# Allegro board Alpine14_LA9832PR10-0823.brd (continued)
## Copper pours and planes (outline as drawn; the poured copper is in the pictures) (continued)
SLEEVE on IN3 (solid shape): 256.39,148.45 256.39,148.03 256.39,147.23 256.56,147.06 256.96,147.06 256.96,146.04 255.31,146.04 254.99,146.36 254.99,148.33 255.24,148.58 256.26,148.58
SLEEVE on TOP: 303.68,155.98 303.68,157.42 303.88,157.62 305.4,157.62 305.52,157.49 305.52,156.59 305.37,156.44 305.05,156.44 304.44,155.83 303.83,155.83
SNUB_1.35V on TOP (solid shape): 184.89,81.78 184.89,79.05 184.76,78.92 183.74,78.92 183.49,79.18 183.49,81.78 183.62,81.91 184.76,81.91
SW1 on TOP (solid shape): 190.85,146.09 190.59,145.83 190.59,144.21 190.52,144.14 190.4,144.14 190.35,144.19 190.35,145.16 190.3,145.2 189.94,145.57 189.94,147.11 189.95,147.12 190.85,147.12
SW1 on TOP (solid shape): 202.54,150.68 202.54,149.6 202.92,149.22 206.68,149.22 206.93,148.96 206.93,142.97 206.45,142.48 204.44,142.48 204.31,142.61 203.3,142.61 203.17,142.74 203.17,144.39 203.3,144.52 204.31,144.52 204.57,144.77 204.57,146.04 204.31,146.29 202.03,146.29 201.9,146.42 201.9,149.09 201.9,149.09 201.65,149.34 201.65,150.74 201.71,150.8 202.41,150.8
SW1 on BOTTOM (solid shape): outline of 89 points within 199.49,141.85 204.95,148.58
SW1 on IN3 (solid shape): 203.43,148.52 203.43,148.2 203.3,148.07 202.41,148.07 201.46,149.03 201.46,149.34 201.65,149.53 202.41,149.53
SW1 on IN3 (solid shape): 191.81,147.37 191.81,146.61 190.47,145.28 190.16,145.28 190.03,145.41 190.03,146.42 191.05,147.44 191.74,147.44
SW2 on TOP (solid shape): 205.84,140.83 205.84,135.75 205.59,135.5 204.37,135.5 202.58,133.7 201.91,133.7 201.81,133.8 201.81,137.79 203.2,139.18 203.2,140.8 203.36,140.96 205.71,140.96
SW2 on TOP (solid shape): 190.53,141.99 190.57,141.94 190.57,140.83 190.62,140.78 190.62,138.9 190.55,138.83 189.71,138.83 189.63,138.9 189.63,139.54 190.17,140.07 190.17,140.81 190.35,140.99 190.35,141.95 190.38,141.99 190.5,141.99
SW2 on BOTTOM (solid shape): 205.52,139.95 205.52,138.99 203.94,137.41 203.94,135.31 203.3,134.67 199.3,134.67 199.2,134.78 199.2,138.13 199.62,138.55 199.62,139.56 200.19,140.14 205.33,140.14
SW2 on IN3 (solid shape): 202.79,137.53 202.79,136.71 202.67,136.58 201.4,136.58 201.33,136.64 201.33,137.6 201.4,137.66 202.67,137.66
SW2 on IN3 (solid shape): 190.98,140.71 190.98,139.95 191.36,139.56 191.36,138.74 190.79,138.74 190.09,139.44 190.09,140.77 190.22,140.9 190.79,140.9
SW_1.35V on TOP (solid shape): 184.63,78.29 184.63,75.94 184.25,75.56 182.22,75.56 182.09,75.68 182.09,76.57 182.22,76.7 183.23,76.7 183.49,76.95 183.49,78.22 183.62,78.35 184.57,78.35
SW_1.35V on TOP (solid shape): 177.16,81.22 177.16,80.36 177.37,80.15 178.24,80.15 178.57,79.82 178.57,76.35 178.41,76.19 177.77,76.19 177.65,76.32 177.65,78.4 177.56,78.48 177.56,78.49 177.48,78.59 177.38,78.67 177.37,78.67 176.71,79.34 176.71,80.83 176.57,80.97 176.31,80.97 176.13,81.15 176.13,81.23 176.2,81.29 177.09,81.29
SW_1.35V on BOTTOM (solid shape): 186.22,81.02 186.22,79.89 186.44,79.67 189.15,79.67 189.53,79.29 189.53,75.68 191.93,73.28 191.93,68 191.49,67.55 187.43,67.55 186.92,68.06 186.92,72.63 183.71,75.84 186.37,75.84 186.37,75.78 186.38,75.73 186.4,75.68 186.42,75.63 186.45,75.59 186.48,75.55 186.53,75.52 186.57,75.49 186.62,75.47 186.67,75.46 186.73,75.45 186.78,75.46 186.83,75.47 186.88,75.49 186.93,75.52 186.97,75.55 187.01,75.59 187.04,75.63 187.06,75.68 187.08,75.73 187.08,75.78 187.08,75.84 187.08,75.89 187.06,75.94 187.04,75.99 187.01,76.03 186.97,76.07 186.93,76.1 186.88,76.13 186.83,76.15 186.78,76.16 186.73,76.17 186.67,76.16 186.62,76.15 186.57,76.13 186.53,76.1 186.48,76.07 186.45,76.03 186.42,75.99 186.4,75.94 186.38,75.89 186.37,75.84 183.71,75.84 183.49,76.06 183.49,81.02 183.73,81.26 185.98,81.26
SW_++VDDRP on TOP (solid shape): 44.68,38.47 44.68,36.95 44.42,36.69 43.66,36.69 43.28,37.08 43.28,38.73 43.53,38.98 44.17,38.98
SW_++VDDRP on TOP (solid shape): 41.31,31.8 41.31,30.98 41.19,30.85 39.09,30.85 38.9,31.04 38.9,31.17 39.66,31.93 41.19,31.93
SW_++VDDRP on BOTTOM (solid shape): 40.26,31.31 40.26,29.56 40.13,29.43 39.14,29.43 39.06,29.51 39.06,30.04 39.12,30.09 39.52,30.09 39.65,30.22 39.65,30.65 39.5,30.8 38.99,30.8 38.91,30.88 38.91,31.21 39.06,31.36 40.21,31.36
SW_++VDDRP on BOTTOM (solid shape): 47.79,41.33 47.79,37.16 47.73,37.1 46.96,37.1 46.87,37.18 46.87,38.25 46.65,38.47 46.22,38.47 46.2,38.5 45.96,38.64 45.72,38.5 45.7,38.47 45.31,38.47 45.12,38.28 45.12,37.08 44.93,36.88 43.15,36.88 41.95,35.68 39.47,35.68 39.41,35.74 39.41,41.77 39.98,42.35 46.77,42.35
SW_+V1.05SP on TOP (solid shape): 149.96,80.13 149.96,78.99 149.9,78.92 148.94,78.92 148.88,78.86 147.93,78.86 147.87,78.92 147.87,79.75 147.93,79.81 148.88,79.81 149.26,80.19 149.9,80.19
SW_+V1.05SP on BOTTOM (solid shape): 151.1,81.08 151.1,79.24 151.04,79.18 149.45,79.18 148.94,78.67 148.94,76.51 148.82,76.38 146.21,76.38 146.02,76.57 146.02,81.02 146.21,81.21 150.98,81.21
U2_BOOT1 on BOTTOM (solid shape): 60.43,38.66 58.97,37.2 58.97,36.5 58.9,36.44 58.01,36.44 57.95,36.5 57.95,36.63 58.01,36.69 58.2,36.69 58.46,36.95 58.46,37.58 59.6,38.73 59.6,40 60.43,40
U2_LGATE1 on TOP (solid shape): 57.95,40.19 57.95,38.15 57.82,38.03 57.25,38.03 57.19,38.09 57.19,40.06 57.38,40.25 57.89,40.25
U2_LGATE1 on TOP (solid shape): 68.43,42.35 68.43,41.46 68.3,41.33 66.65,41.33 66.65,41.77 67.35,42.47 68.3,42.47
U2_LGATE1 on BOTTOM (solid shape): 69.25,42.41 69.25,41.39 69.13,41.27 68.11,41.27 67.98,41.39 67.98,42.41 68.11,42.54 69.13,42.54
U2_LGATE1 on BOTTOM (solid shape): 74.84,42.41 74.84,41.39 74.71,41.27 73.7,41.27 73.57,41.39 73.57,42.41 73.7,42.54 74.71,42.54
U2_LGATE1 on BOTTOM (solid shape): 58.01,39.36 57.82,39.17 57.82,38.33 57.38,37.89 57.38,36.82 57.3,36.74 57.17,36.74 57.1,36.82 57.1,39.23 57.4,39.54 57.4,40.06 58.01,40.06
U2_LGATE1 on IN1 (solid shape): 74.08,42.35 74.08,41.46 73.95,41.33 68.11,41.33 67.98,41.46 67.98,42.35 68.11,42.47 73.95,42.47
U2_LGATE2 on TOP (solid shape): 56.3,39.81 56.3,38.03 56.17,37.9 55.54,37.9 55.47,37.96 55.47,38.92 55.35,39.04 55.35,39.87 55.41,39.93 56.17,39.93
U2_LGATE2 on TOP (solid shape): 56.36,44.25 56.36,43.43 56.23,43.3 55.47,43.3 55.22,43.04 55.22,42.54 54.2,42.54 54.2,43.81 54.84,44.44 56.17,44.44
U2_LGATE2 on BOTTOM (solid shape): 51.41,44.38 51.41,43.36 51.28,43.23 50.27,43.23 50.14,43.36 50.14,44.38 50.27,44.5 51.28,44.5
U2_LGATE2 on BOTTOM (solid shape): 57.12,44.38 57.12,43.36 57,43.23 55.98,43.23 55.85,43.36 55.85,44.38 55.98,44.5 57,44.5
U2_LGATE2 on IN1 (solid shape): 56.36,44.25 56.36,43.49 56.17,43.3 50.27,43.3 50.14,43.43 50.14,44.31 50.27,44.44 56.17,44.44
U2_PHASE1 on BOTTOM (solid shape): 59.22,38.73 58.14,37.65 58.14,37.08 57.82,36.76 57.7,36.76 57.63,36.82 57.63,37.84 58.08,38.28 58.08,39.11 58.33,39.36 58.33,40.06 59.22,40.06
U2_PHASE1 on BOTTOM (solid shape): 75.86,51.93 77.06,51.93 77.32,51.68 77.32,48.76 78.08,48 81.13,48 81.19,47.93 81.19,46.35 80.94,46.09 79.35,46.09 78.71,45.46 78.71,43.62 78.46,43.36 68.49,43.36 68.24,43.62 68.24,53.01 68.81,53.59 74.21,53.59
U2_PHASE1 on IN1 (solid shape): 60.55,39.3 60.55,38.41 60.17,38.03 58.27,38.03 58.01,38.28 58.01,39.04 58.39,39.42 60.43,39.42
U2_PHASE1 on IN1 (solid shape): 70.49,49.23 70.49,48.69 69.24,47.43 68.6,47.43 68.45,47.58 68.45,48.17 69.56,49.27 70.45,49.27
U2_PHASE2 on TOP (solid shape): 52.04,46.98 52.04,46.47 51.79,46.22 51.28,46.22 50.27,47.24 50.27,48.06 50.46,48.25 50.77,48.25
U2_PHASE2 on TOP (solid shape): 55.16,38.92 55.16,38.09 55.03,37.96 54.46,37.96 53.25,39.17 53.25,39.74 53.5,40 54.08,40
U2_PHASE2 on BOTTOM (solid shape): 54.9,39.42 55.22,39.11 55.22,38.09 55.09,37.96 54.58,37.96 54.39,38.15 54.39,38.73 54.01,39.11 54.01,40.19 54.9,40.19
U2_PHASE2 on BOTTOM (solid shape): 60.36,56 60.36,54.47 60.74,54.09 62.01,54.09 62.14,53.97 62.14,51.11 60.93,49.9 60.93,45.58 60.68,45.33 50.96,45.33 50.96,46.73 50.52,47.17 48.68,47.17 48.42,47.43 48.42,49.33 50.08,49.33 50.46,49.71 50.46,56.06 50.71,56.32 60.04,56.32
U2_UGATE1 on BOTTOM (solid shape): 76.75,53.46 77.06,53.46 77.25,53.27 77.25,52.63 77.13,52.51 75.86,52.51 75.48,52.89 75.48,53.65 75.67,53.84 76.36,53.84
U2_UGATE1 on IN1 (solid shape): 61.25,37.36 61.25,36.15 61.19,36.09 59.47,36.09 59.22,36.34 59.22,37.36 59.33,37.47 61.14,37.47
U2_UGATE1 on IN1 (solid shape): 76.49,53.71 76.49,52.76 75.35,51.62 74.59,51.62 74.52,51.68 74.52,52.76 75.67,53.9 76.3,53.9
U2_UGATE2 on TOP (solid shape): 62.08,56.06 62.08,55.43 61.89,55.24 60.04,55.24 60.04,56.25 61.89,56.25
U2_UGATE2 on TOP (solid shape): 52.74,38.28 53.19,38.28 53.57,37.9 53.57,36.88 53.44,36.76 52.74,36.76 51.41,38.09 51.41,38.6 51.54,38.73 52.3,38.73
U2_UGATE2 on BOTTOM (solid shape): 53.54,38.09 53.54,36.82 53.41,36.69 53.19,36.69 52.81,37.08 52.81,38.09 52.87,38.15 53.47,38.15
U2_UGATE2 on BOTTOM (solid shape): 62.14,55.87 62.14,54.86 62.01,54.73 61,54.73 60.87,54.86 60.87,55.87 61,56 62.01,56
UG_3V on TOP (solid shape): 204.31,142.17 204.31,141.25 204.18,141.12 203.32,141.12 203.17,141.27 203.17,142.17 203.3,142.29 204.19,142.29
UG_3V on TOP (solid shape): 191.58,141.75 191.58,141.41 192.06,140.94 192.06,139.94 191.96,139.84 191.59,139.84 191.49,139.94 191.49,140.73 191.15,141.07 191.15,141.93 191.21,141.99 191.35,141.99
UG_3V on IN3 (solid shape): 192.95,139.95 192.89,139.88 191.68,139.88 191.55,140.01 191.55,140.77 191.68,140.9 192.95,140.9
UG_3V on IN3 (solid shape): 204.32,142.17 204.32,141.98 203.24,140.9 202.67,140.9 202.54,141.02 202.54,141.6 203.3,142.36 204.13,142.36
UG_5V on TOP (solid shape): 204.31,145.72 204.31,144.9 204.19,144.77 203.3,144.77 203.17,144.9 203.17,145.72 203.3,145.85 204.19,145.85
UG_5V on TOP (solid shape): 191.97,145.63 191.97,144.8 191.78,144.61 191.51,144.61 191.44,144.53 191.44,144.21 191.37,144.14 191.22,144.14 191.15,144.21 191.15,145.26 191.62,145.73 191.88,145.73
UG_5V on IN3 (solid shape): 204.32,145.91 204.32,145.41 204.13,145.22 202.03,145.22 201.65,145.6 201.65,146.1 204.13,146.1
UG_5V on IN3 (solid shape): 193.01,146.74 193.01,145.72 191.93,144.64 191.49,144.64 191.43,144.71 191.43,145.85 192,146.42 192,146.68 192.19,146.87 192.89,146.87
UG_+VDDRP on TOP (solid shape): 40.61,30.66 40.61,29.65 40.55,29.58 38.58,29.58 38.39,29.77 38.39,30.53 38.58,30.73 40.55,30.73
UG_+VDDRP on TOP (solid shape): 46.46,37.9 46.46,35.68 46.14,35.36 45.44,35.36 45.31,35.49 45.31,37.84 45.57,38.09 46.27,38.09
UG_+VDDRP on BOTTOM (solid shape): 46.39,37.9 46.39,36.95 46.27,36.82 45.5,36.82 45.31,37.01 45.31,37.84 45.5,38.03 46.27,38.03
USX2064_RBIAS on TOP (solid shape): 173.96,119.05 173.96,117.91 174.54,117.34 174.54,116.7 174.73,116.51 175.11,116.51 175.23,116.39 175.23,115.75 174.73,115.75 174.31,116.17 174.27,116.21 174.23,116.25 173.71,116.77 173.71,119.05 173.77,119.12 173.9,119.12
N07710 on TOP (solid shape): 121.61,149.71 121.61,147.96 121.31,147.67 119.82,147.67 119.48,148 119.48,148.98 120.32,149.81 121.5,149.81
N07808 on TOP (solid shape): 141.64,163.06 142.72,163.06 143.55,162.23 144.94,162.23 145.2,161.98 145.2,161.34 145.07,161.22 144.44,161.22 143.86,160.65 143.23,160.65 143.1,160.77 143.1,161.85 142.4,162.55 141.13,162.55 140.82,162.87 139.42,162.87 139.23,163.06 139.23,163.44 139.55,163.76 140.94,163.76
N07946 on TOP (solid shape): 134.59,167.76 134.59,165.5 134.47,165.37 133.17,165.37 132.82,165.01 132.82,164 132.66,163.85 129.69,163.85 129.59,163.95 129.59,166.13 129.58,166.15 129.58,167.5 129.63,167.55 130.8,167.55 130.91,167.44 130.91,166.81 131.04,166.68 131.74,166.68 131.86,166.81 131.86,167.69 132.05,167.89 134.47,167.89
N16932721 on TOP (solid shape): 133.77,83.58 133.77,82.06 133.73,82.02 132.74,82.02 132.5,82.64 132.26,82.02 130.99,82.02 130.72,82.29 130.72,83.42 131,83.7 133.65,83.7
N19821558 on BOTTOM (solid shape): 40.13,28.87 40.13,28.06 40.06,27.98 38.1,27.98 38.05,28.03 38.05,28.9 38.07,28.92 40.08,28.92
N19821679 on BOTTOM (solid shape): 48.23,36.19 48.23,34.41 46.58,34.41 46.58,36.25 46.77,36.44 47.98,36.44
N19844564 on BOTTOM (solid shape): 73.32,20.37 73.32,19.1 73.25,19.04 70.71,19.04 70.33,19.42 70.33,20.31 70.46,20.44 73.25,20.44
N19847781 on TOP (solid shape): 192.12,147.88 189.97,147.88 189.97,148.52 192.12,148.52
N19847834 on TOP (solid shape): 192.01,138.17 192.01,137.56 191.88,137.43 189.65,137.43 189.57,137.51 189.57,138.14 189.7,138.27 191.91,138.27
N19847903 on TOP (solid shape): 201.08,150.87 201.08,149.91 200.95,149.79 198.28,149.79 198.09,149.98 198.09,150.87 198.22,150.99 200.95,150.99
N19847904 on TOP (solid shape): 200.13,134.74 201.24,134.74 201.31,134.67 201.31,133.78 201.25,133.73 199.62,133.73 199.31,134.04 198.16,134.04 198.16,135.06 199.81,135.06
N19848836 on TOP (solid shape): 179.99,79.47 179.99,77.55 179.81,77.38 179.15,77.38 178.92,77.61 178.92,79.51 178.96,79.54 179.92,79.54
N19849916 on TOP (solid shape): 151.29,80.89 151.29,80.45 151.17,80.32 148.88,80.32 148.75,80.45 148.75,80.95 148.82,81.02 151.17,81.02
N19850655 on TOP (solid shape): 103.61,160.71 103.92,160.39 104.49,160.39 104.56,160.33 104.56,159.38 102.97,159.38 102.97,161.66 103.61,161.66
N19850750 on TOP (solid shape): 110.21,165.15 110.21,157.28 110.02,157.09 106.02,157.09 105.76,157.34 105.76,160.39 105.38,160.77 104.37,160.77 104.37,161.66 106.21,161.66 106.84,162.3 106.84,165.35 107.03,165.54 109.83,165.54
N19850750 on TOP (solid shape): 107.23,145.85 107.23,145.41 107.61,145.03 109.57,145.03 109.64,144.96 109.64,144.83 109.57,144.77 105.96,144.77 105.76,144.96 105.76,145.85 105.96,146.04 107.03,146.04
N19850750 on BOTTOM (solid shape): 109.51,164.65 109.51,159.31 108.94,158.74 105.07,158.74 104.3,159.5 100.89,159.5 100.61,159.78 100.61,164.71 100.74,164.84 109.32,164.84
N19850750 on IN3 (solid shape): 106.72,145.15 106.34,144.77 105.96,144.77 105.7,145.03 105.7,147.57 106.72,147.57
N19850750 on IN3 (solid shape): 107.54,159.73 107.54,158.58 106.91,157.95 106.21,157.95 106.15,158.01 106.15,158.58 106.53,158.96 106.53,159.66 106.78,159.92 107.35,159.92
N19850905 on TOP (solid shape): 106.27,146.23 105.83,146.23 105.64,146.04 105.64,144.83 104.49,144.83 103.92,145.41 103.92,147.12 106.27,147.12
N22916336 on TOP (solid shape): 64.74,90.35 65.06,90.35 65.19,90.48 67.57,90.48 67.75,90.3 67.75,89.14 67.63,89.02 65.01,89.02 64.98,89.04 64.98,89.06 64.63,89.36 64.28,89.05 64.27,89.01 63.3,89.01 63.26,89.05 63.26,89.07 63.15,89.31 62.91,89.41 62.89,89.41 62.77,89.54 62.77,91.11 63.98,91.11
N22916336 on BOTTOM (solid shape): 64.19,90.98 64.29,90.86 64.44,90.82 64.51,90.79 64.54,90.72 64.87,90.4 65.2,90.72 65.23,90.79 65.3,90.82 65.38,90.83 65.46,90.87 65.92,90.87 66.09,90.82 66.26,90.87 66.76,90.87 66.92,90.82 67.09,90.86 67.1,90.87 67.19,90.87 67.29,90.77 67.29,90.09 66.4,89.2 65.34,89.2 65.34,89.2 64.88,89.2 64.63,89.33 64.37,89.2 64.06,89.2 63.34,89.92 63.34,90.75 63.45,90.86 63.48,90.85 63.63,90.82 63.77,90.86 63.78,90.87 63.87,90.87 63.98,90.98
N23032286 on TOP (solid shape): 68.68,85.78 73.89,85.78 74.08,85.59 74.08,84.89 72.05,84.89 71.86,84.7 68.11,84.7 67.98,84.83 67.98,85.78 68.17,85.97 68.49,85.97
N23621118 on BOTTOM (solid shape): 50.08,44.89 49.82,44.63 48.61,44.63 48.42,44.82 48.42,46.66 50.08,46.66
N23709542 on BOTTOM (solid shape): 81.06,43.68 80.68,43.3 79.54,43.3 79.41,43.43 79.41,45.33 81.06,45.33
N24520734 on TOP (solid shape): 124.52,151.94 124.52,150.35 124.41,150.23 123.49,150.23 122.58,151.14 122.58,152.17 122.87,152.46 122.87,152.47 123.99,152.47
N24856259 on TOP (solid shape): 150.97,134.24 151.02,134.12 151.11,134.03 151.11,133.03 150.88,132.81 147.51,132.81 147.26,133.06 147.26,134.38 147.52,134.65 150.56,134.65
N24856273 on TOP (solid shape): 154.66,133.44 154.66,131.26 153.76,130.36 152.54,130.36 152.38,130.52 152.38,131.73 151.61,132.5 151.61,133.25 152.02,133.66 154.44,133.66
N24972963 on TOP (solid shape): 112.2,154.13 112.2,153.26 112.42,153.03 112.42,151.82 112.37,151.77 111.11,151.77 110.88,152 110.88,152.55 110.78,152.66 110.09,152.66 109.98,152.77 109.98,153.32 111.17,154.51 111.82,154.51
N25025878 on TOP (solid shape): 128.79,127.16 128.79,125.91 128.45,125.57 126.82,125.57 125.65,126.74 125.65,127.71 125.91,127.98 127.98,127.98

Small or netless copper shapes (teardrops, artwork), in the pictures only: 25 on TOP, 307 on BOTTOM

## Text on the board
Ref Des/Silkscreen Bottom: DIMM A | DDR3L | LOW VOLTAGE | DIMM B | H18 | H19 | H20
User.Comments: LA-9832P | Juce_Feng | 2013-08-23 | VAW30 | 2014-08-23 | 1.0(A00) | +1.5V_GPU | GND | +GPU_CORE | +VCC_CORE | +1.05V_RUN | +3.3V_ALW_PCH | +1.05V_M | +5V_RUN | +1.05V_MP | +5V_ALW | +3.3V_RUN | +3.3V_ALW | +DOCK_PWR_BAR | GNDA
Ref Des/Silkscreen Top: C | B | A | H17 | H22 | H21 | H23
BODY_CENTER: GND | +1.5_GPU | +5V_ALW | +1.05V_RUN | +VCC_CORE | +1.05V_M | +3.3V_ALW_PCH | +3.3V_ALW | +5V_RUN
User.13: (0,0) | 17,5 | 68,4 | 79,11 | 78,5 | 82,83 | 88,8 | 92,26 | 94,21 | 96,42 | 104,11 | 148,45 | 162,93 | 175,4 | 183,45 | 186,95 | 187,8 | 47,8 | ~ | 281,35 | 157,5 | 140,42 | 113,01 | 103,28 | 99,05 | 87,55 | 70 | 19,3 | 23,79 | 96,97 | 4,85 | 23,2 | 95,15 | 108,43 | 110,2 | 155,75 | 167,5
User.14: (0,0) | 10,78 | 37,57 | 43,6 | 13,54 | 76,94 | 83,5 | 86,76 | 29,48 | 21,28 | 7,24 | 145,75 | 160,87 | 174 | 195,5 | 209,61 | 201,5 | 228,39 | 272,41 | 304,05 | 173 | 164 | 112,21 | 107,33 | 90,8 | 79,35 | 60,32 | 56,69 | 46,1 | 16,97 | 23,68 | 8,35 | 38,99 | 122,95 | 128,95 | 157,16 | 159,23 | 167,4
User.15: (0,0) | 37,5 | 56,35 | 73,01 | 72,3 | 75,35 | 78,3 | 82,85 | 111,6 | 88,5 | 89,4 | 92,5 | 99,17 | 109,17 | 7 | 37 | 129,17 | 8,35 | 6,98 | 136,4 | 154,3 | 156 | 170,5 | 188,93 | 190,65 | 191,85 | 195,65 | 10 | 10,5 | 26,2 | 8,2 | 283,7 | 290,2 | 22,8 | 27,6 | 6 | 11,5 | 14,7 | 19,4 | 50 | 3,8 | 9,2 | 154,85 | 144,85 | 117,93 | 108,85 | 96,06 | 80,74 | 75,7 | 69 | 66,5 | 60,1 | 35,25 | 33 | 28,85 | 14,2 | 24,1 | 10,74 | 14,74 | 10,98 | 4 | 8 | 7,2 | 10,2 | 10,7 | 3 | 4,64 | 4,74 | 24,4 | 9 | 65,2 | 4,5 | 66,3 | 5,4 | 78,5 | 83,5 | 94,12 | 115,1 | 150,9 | 168 | 172,4
User.16: (0,0) | 2,1 | 25,96 | 29,6 | 30,4 | 43,6 | 2 | 74,27 | 76,27 | 83,4 | 82,15 | 88,4 | 97,85 | 97,7 | ~ | 101,9 | 107,38 | 121 | H=0 | 117,28 | 120,5 | 124,28 | 131,4 | 129,09 | 135,55 | 147,1 | 159,4 | 15,8 | 183,2 | 191,45 | 196,65 | 8,39 | 208,5 | 218,9 | 221,65 | 9,53 | 246,85 | 256,15 | 6,82 | 268,45 | 280,5 | 21,44 | 300,7 | 57,9 | 1 | 0,5 | 14,8 | 2-R5,5 | R2 | 4-168,8 | 167,85 | 161,05 | 156,5 | 12,5 | 155,6 | 105,68 | 101,45 | 82,6 | 67,45 | 65,45 | 60,45 | 56,69 | 39,8 | 33 | 22 | 6 | 11,98 | 9,9 | 1,5 | 3,14 | 14,74 | 13,6 | 9 | 7,2 | 4,35 | 72,6 | 75,35 | 81,25 | 148 | 157 | 162 | 2-R7,9 | 11
User.17: n | 6 | 3,3 | (0,0) | 8 | 2,8 | 5 | 1,2 | 2,5
User.18: (0,0) | 8 | 5 | n | 6 | 3,3 | 2,8 | 2,5
User.19: (0,0) | 37,5 | 50,57 | 56,35 | 69,97 | 73,01 | 75,35 | 108,67 | 37 | 119,17 | 7 | 6,98 | 136,4 | 154,3 | 162,15 | 156 | 175,95 | 9,5 | 8,35 | 188,93 | 185,1 | 191,85 | 14,5 | 8,2 | 283,7 | 10 | 301,51 | 304,77 | 27,6 | 6 | 11,5 | 14,7 | 3,8 | 1,77 | 9,2 | R4 | 4-R2 | 101,85 | 96,06 | 80,74 | 75,7 | 74,75 | 66,71 | 66,5 | 42,74 | 29,24 | 2,5 | 10,74 | 14,2 | 76 | 8 | 4 | 7,2 | 10,2 | 10,7 | 4,64 | 3 | 9 | 65,2 | 83,5 | 94,12 | 115,1 | 150,9 | 172,4
User.20: (0,0) | 83,4 | 103,5 | 120,5 | 129,4 | 131,4 | 135,55 | 208,5 | 15,8 | 8 | 2,4 | 57,9 | 112,25 | 0,5 | 15,3 | Paint mark Line | 167,85 | 13,6 | 161,05 | 155,6 | 10,35 | 81,25 | 30 | 27,6 | 1,85 | 14,74 | 4,6 | 2,25 | 1,95 | 37,59 | 72,51 | 7,9
User.21: (0,0) | 0,6 | 1,2 | 0,95 | 13,6 | 1,7 | 30,6 | 2-48,58 | 72,55 | 79,58 | 78,5 | 97,7 | 121,07 | 190,7 | 195,65 | 198,15 | 208,68 | 209,76 | 17,2 | 20,9 | 235,26 | 281,85 | 283,75 | 314,35 | 22,4 | 18,7 | 3,5 | R31 | R1 | 34-R1,5 | R1,8 | R4 | 175,3 | 174,65 | 173,5 | 165,1 | 158,6 | 142,24 | 137,24 | 107,24 | 106,24 | 102,55 | 87,05 | 82,6 | 69,1 | 39,02 | 9,25 | 3,35 | 2,2 | 1 | 9,9 | 13,5 | 61,95 | 72,2 | 118,1 | 143,6 | 177,2 | R2,75
User.22: n | 6 | 3,3 | (0,0) | 8 | 2,3 | 5 | 1,2 | 2,8 | 2,5
User.23: (0,0) | 8 | 5 | n | 6 | 3,3 | 2,3 | 2,8 | 2,5
User.24: (0,0) | 17,5 | 68,4 | 79,11 | 78,5 | 82,83 | 88,8 | 92,26 | 94,21 | 96,42 | 104,11 | 148,45 | 162,93 | 175,4 | 183,45 | 186,95 | 187,8 | 47,8 | ~ | 281,35 | 157,5 | 140,42 | 113,01 | 103,28 | 99,05 | 87,55 | 70 | 19,3 | 23,79 | 96,97 | 4,85 | 23,2 | 95,15 | 108,43 | 110,2 | 155,75 | 167,5
User.25: (0,0) | 10,78 | 37,57 | 43,6 | 13,54 | 76,94 | 83,5 | 86,76 | 29,48 | 21,28 | 7,24 | 145,75 | 160,87 | 174 | 195,5 | 209,61 | 201,5 | 228,39 | 272,41 | 304,05 | 173 | 164 | 112,21 | 107,33 | 90,8 | 79,35 | 60,32 | 56,69 | 46,1 | 16,97 | 23,68 | 8,35 | 38,99 | 122,95 | 128,95 | 157,16 | 159,23 | 167,4
User.26: (0,0) | 37,5 | 56,35 | 73,01 | 72,3 | 75,35 | 78,3 | 82,85 | 88,5 | 89,4 | 92,5 | 99,17 | 109,17 | 7 | 37 | 129,17 | 8,35 | 6,98 | 136,4 | 154,3 | 156 | 170,5 | 188,93 | 190,65 | 191,85 | 195,65 | 10 | 10,5 | 8,2 | 283,7 | 290,2 | 27,6 | 6 | 11,5 | 14,7 | 3,8 | 9,2 | 50 | 154,85 | 151,5 | 144,85 | 118,1 | 117,93 | 108,85 | 96,06 | 80,74 | 75,7 | 69 | 66,5 | 60,1 | 35,25 | 33 | 28,85 | 14,2 | 24,1 | 10,74 | 14,74 | 10,98 | 4 | 8 | 7,2 | 10,2 | 10,7 | 3 | 4,64 | 4,74 | 24,4 | 9 | 65,2 | 66,3 | 83,5 | 94,12 | 115,1 | 150,9 | 168 | 172,4
User.27: (0,0) | 2,1 | 25,96 | 29,6 | 30,4 | 43,6 | 2 | 74,27 | 76,27 | 83,4 | 82,15 | 88,4 | 97,85 | 97,7 | ~ | 101,9 | 107,38 | 121 | H=0 | 117,28 | 120,5 | 124,28 | 131,4 | 129,09 | 135,55 | 147,1 | 159,4 | 15,8 | 183,2 | 191,45 | 196,65 | 8,39 | 208,5 | 218,9 | 221,65 | 9,53 | 246,85 | 256,15 | 6,82 | 268,45 | 280,5 | 21,44 | 300,7 | 57,9 | 1 | 0,5 | 14,8 | 2-R5,5 | R2 | 4-168,8 | 167,85 | 161,05 | 156,5 | 12,5 | 155,6 | 105,68 | 101,45 | 82,6 | 67,45 | 65,45 | 60,45 | 56,69 | 39,8 | 33 | 22 | 6 | 11,98 | 9,9 | 1,5 | 3,14 | 14,74 | 13,6 | 9 | 7,2 | 4,35 | 72,6 | 75,35 | 81,25 | 148 | 157 | 162 | 2-R7,9 | 11
User.28: n | 6 | 3,3 | (0,0) | 8 | 2,3 | 5 | 1,2 | 2,8 | 2,5
User.29: (0,0) | 8 | 5 | n | 6 | 3,3 | 2,3 | 2,8 | 2,5
User.30: (0,0) | 37,5 | 50,57 | 56,35 | 69,97 | 73,01 | 75,35 | 108,67 | 37 | 119,17 | 7 | 6,98 | 136,4 | 154,3 | 162,15 | 156 | 175,95 | 9,5 | 8,35 | 188,93 | 185,1 | 191,85 | 14,5 | 8,2 | 283,7 | 10 | 301,51 | 304,77 | 27,6 | 6 | 11,5 | 14,7 | 3,8 | 1,77 | 9,2 | R4 | 4-R2 | 101,85 | 96,06 | 80,74 | 75,7 | 74,75 | 66,71 | 66,5 | 42,74 | 29,24 | 2,5 | 10,74 | 14,2 | 76 | 8 | 4 | 7,2 | 10,2 | 10,7 | 4,64 | 3 | 9 | 65,2 | 83,5 | 94,12 | 115,1 | 150,9 | 172,4
User.31: (0,0) | 12,39 | 12 | 83,4 | 103,5 | 120,5 | 129,4 | 131,4 | 135,55 | 208,5 | 15,8 | 8 | 2,4 | 57,9 | 112,25 | 0,5 | 15,3 | Paint mark Line | 167,85 | 13,6 | 161,05 | 155,6 | 10,35 | 81,25 | 30 | 27,6 | 3 | 14,74 | 4,6 | 2,25 | 1,95 | 37,59 | 72,51 | 7,9
User.32: (0,0)
User.45: 4 / 6.5 | FIGURE | SIZE | 7.0 | 8.0 | 10.0 | 22.0 | 28.0 | 39.0 | 47.0 | 91.0 | 110.0 | 130.0 | 169.0 | 181.0 | 197.0 | 26.0 | 31.0 | 35.0 | 40.0 | 43.0 | 63.0 | 71.0 | 39.0x33.0 | 45.0x37.0 | 63.0x35.0 | 69.0x20.0 | 73.0x31.0 | 75.0x37.0 | 102.0x31.0 | 112.0x39.0 | 114.0x39.0 | 118.0x33.0 | 130.0x110.0 | 75.0x47.0 | DRILL CHART: TOP to BOTTOM | ALL UNITS ARE IN MILS | PLATED | NON-PLATED | QTY | 294 | 6335 | 125 | 19 | 9 | 13 | 1 | 3 | 7 | 4 | 2 | 6
